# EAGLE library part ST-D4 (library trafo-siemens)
TRANSFORMER
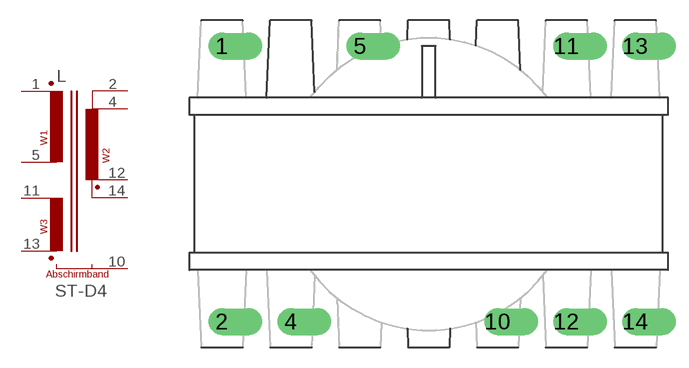
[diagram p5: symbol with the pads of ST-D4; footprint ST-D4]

Designator prefix L

## ST-D4  [ST-D4]
1  1A  pas
2  2E  pas
4  2E1  pas
5  1E  pas
10  SCH  pas
11  3E  pas
12  2A  pas
13  3A  pas
14  2A1  pas

## Footprint ST-D4 (pad centres in mm)
TRANSFORMER
drill 1.321 offset: 1 -15.24,10.16; 2 -15.24,-10.16; 4 -10.16,-10.16; 5 -5.08,10.16; 10 5.08,-10.16; 11 10.16,10.16; 12 10.16,-10.16; 13 15.24,10.16; 14 15.24,-10.16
